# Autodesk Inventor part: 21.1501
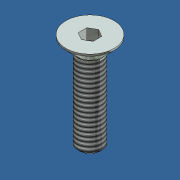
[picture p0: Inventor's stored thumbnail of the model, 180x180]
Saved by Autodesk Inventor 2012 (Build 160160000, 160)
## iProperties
Created: 2006-12
Part Number: 21.1501
Material: Steel
Description: M4x16 C'SUNK
Document SubType Name: Modeling
Standard: DIN 7991
Designer: Andy Moles
Standards Organization: DIN
Language: en-US
Size Designation: M4x16
Categories: <MemberInstance Version="R10.0.0"><Categories><Category DisplayName="Fasteners" InternalName="e4da775c-781d-43d5-af7c-5136215cf5a6" Mnemonic="FSTN"><Category Di
Density: 7.85 g/cm^3
Vendor: S
Mass: 1.84809 g
Surface Area: 3.08594 cm^2
Volume: 0.235425 cm^3
Author: Andy Moles
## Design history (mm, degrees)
node "Sketch1"
node "WorkPoint1"
sketch "Sketch2"
  geometry: L1 (-2, -16)-(0, -16); L2 (-2, -2.3)-(-2, -16); L3 (-4, -0.3)-(-2, -2.3); L4 (-4, 0)-(-4, -0.3); L5 (0, 0)-(-4, 0); L6 (0, -16)-(0, 0); L7 (0, -16)-(0, 0); L8 (0, -17.6)-(0, 4.8) reference; L9 (0.4, 0)-(-5.2, 0) reference
  constraints: 14 end point, 3 vertical, 2 horizontal
  dimensions: "d1" = 45 deg angle of L3 L6; "d3" = 4 distance of L5.start L4.start (= 0.5 x dk); "d5" = 2 distance of L1.start L1.end (= 0.5 x NND); "d7" = 16 distance of L1.end L5.start (= NLG); "ParC" = 0.3 distance of L4.start L3.start; "d22" = 0 distance between parallel lines of L8 L6; "d23" = 0 distance between parallel lines of L9 L5
fillet "Fillet1" dims "d18" = 0.2 (= r)
chamfer "Chamfer1" distance "d19" = 0.35 (= 0.5 x PTC); stored, may be unused: angle "d20" = 45 deg, second distance "d39" = 0.35 (= 0.5 x PTC)
node "MSC_A1"
node "MSC_PF1"
node "MSC_PT1"
body "Solid1"
revolve "Revolution1" stored, may be unused: angle "d8" = 360 deg
sketch "Sketch3"
  geometry: L1 (-1.25, 0.722)-(-1.25, -0.722); L2 (0, 1.443)-(-1.25, 0.722); L3 (1.25, 0.722)-(0, 1.443); L4 (1.25, -0.722)-(1.25, 0.722); L5 (0, -1.443)-(1.25, -0.722); L6 (-1.25, -0.722)-(0, -1.443); C1 r 1.25 at (0, 0); C2 r 2 at (0, 0) reference
  constraints: 12 end point, 6 tangent, 2 parallel, 2 vertical, 1 centre point, 1 concentric
  dimensions: "d11" = 2.5 diameter of C1 (= ParS); "d13" = 120 deg angle of L1 L2; "d15" = 120 deg angle of L6 L1
extrude "Extrusion1" cut sketch "Sketch3" distance "d16" = 1.8 (= ParT); taper "d17" = 0 deg
thread "Thread1" dims "d35" = 0, "b" = 13
other parameters: "NND" = 4 [user parameter; used in 2 equation terms], "PTC" = 0.7 [user parameter; used in 2 equation terms], "dk" = 8 [user parameter; used in 1 equation term], "ParK" = 2.3 [user parameter], "ParS" = 2.5 [user parameter; used in 1 equation term], "ParT" = 1.8 [user parameter; used in 1 equation term], "r" = 0.2 [user parameter; used in 1 equation term], "NLG" = 16 [user parameter; used in 1 equation term], "d0" = 45 deg (derived), "d2" = 3 (derived), "d4" = 1.5 (derived), "d6" = 8 (derived), "d9" = 0, "d10" = 2 (derived), "d12" = 120 deg (derived), "d14" = 120 deg (derived), "d37" = 0, "d38" = 0, "d40" = 0, "d41" = 0, "d42" = 0, "THREADDIA" = 4 (= NND) [user parameter]
